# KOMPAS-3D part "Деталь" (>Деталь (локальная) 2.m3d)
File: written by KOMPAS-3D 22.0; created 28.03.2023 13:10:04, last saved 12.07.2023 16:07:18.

Document properties: Автор: Admin; Полное имя файла: C:\Users\yna_n\AppData\Local\Temp\KOMPAS-3D\ktff-d82d-58a0-8265\_Деталь (локальная) 2.m3d

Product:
- Part/product: Деталь
    Масса: 0.121463

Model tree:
1. Эскиз:1
2. Эскиз:24
3. Элемент выдавливания:85
     Расстояние 1 = 156
4. Элемент выдавливания:86
     Расстояние 1 = 50
5. Булева операция:1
